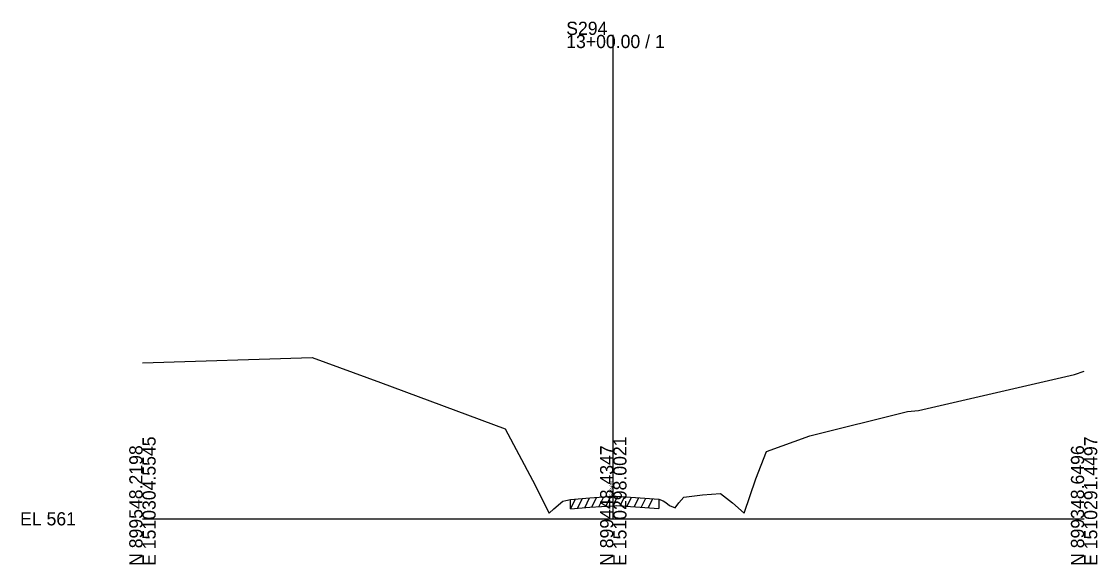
# Model space of a CAD drawing. Extents: x 974 to 2203, y -10 to 19041.
# Drawn here: x 974.3 to 1202.8, y 5990.3 to 6105.6 of the extents above; entities that cross this region are included whole.
import ezdxf

# ---------------------------------------------------------------- set-up
doc = ezdxf.new("R2010")
doc.units = 0
for name, color, linetype in [('RD_GPK_XS_Cell', 7, 'Continuous'), ('RD_XS_ExGround', 7, 'Continuous'), ('RD_XS_ExPaveRet', 7, 'Continuous'), ('RD_XS_TX_Elev_EX', 7, 'Continuous')]:
    doc.layers.add(name, color=color, linetype=linetype)

msp = doc.modelspace()

# ---------------------------------------------------------------- linework, layer by layer
at = {"layer": 'RD_GPK_XS_Cell'}
for p, q in [((1100, 6000), (1100, 6102.73)), ((1000, 6000), (1100, 6000)), ((1100, 6000), (1200, 6000))]:
    msp.add_line(p, q, dxfattribs=at)
at = {"layer": 'RD_XS_ExGround'}
msp.add_lwpolyline([(1000, 6033.09), (1036.04, 6034.24), (1050.58, 6028.97), (1077.02, 6019.13), (1082.85, 6008.21), (1086.36, 6001.19), (1087.39, 6002.09), (1089.31, 6003.76), (1089.89, 6003.9), (1090.93, 6004.11), (1095.05, 6004.45), (1100, 6004.78), (1100.59, 6004.82), (1105.71, 6004.44), (1109.68, 6004.19), (1110.57, 6003.81), (1111.19, 6003.47), (1111.91, 6002.86), (1113.14, 6002.35), (1113.95, 6003.41), (1114.95, 6004.62), (1118.96, 6005.06), (1122.74, 6005.34), (1125.32, 6003.39), (1127.82, 6001.2), (1130.28, 6008.47), (1132.52, 6014.27), (1141.73, 6017.61), (1162.5, 6022.77), (1164.82, 6023.02), (1197.93, 6030.66), (1200, 6031.33)], dxfattribs=at)
at = {"layer": 'RD_XS_ExPaveRet'}
for p, q in [((1090.93, 6002.11), (1091.97, 6004.19)), ((1090.93, 6002.11), (1090.93, 6004.11)), ((1092.43, 6002.23), (1093.47, 6004.32)), ((1093.93, 6002.35), (1094.97, 6004.44)), ((1095.43, 6002.47), (1096.46, 6004.54)), ((1096.93, 6002.57), (1097.96, 6004.64)), ((1098.43, 6002.67), (1099.46, 6004.74)), ((1099.93, 6002.77), (1100.94, 6004.79)), ((1101.43, 6002.76), (1102.39, 6004.69)), ((1102.93, 6002.65), (1103.89, 6004.58)), ((1104.43, 6002.54), (1105.39, 6004.47)), ((1105.93, 6002.43), (1106.89, 6004.37)), ((1107.43, 6002.33), (1108.39, 6004.27)), ((1109.68, 6004.19), (1109.68, 6002.19)), ((1090.93, 6002.11), (1095.05, 6002.45)), ((1095.05, 6002.45), (1100, 6002.78)), ((1100, 6002.78), (1100.59, 6002.82)), ((1100.59, 6002.82), (1105.71, 6002.44)), ((1105.71, 6002.44), (1109.68, 6002.19))]:
    msp.add_line(p, q, dxfattribs=at)

# ---------------------------------------------------------------- texts
at = {"layer": 'RD_GPK_XS_Cell'}
for s, p in [('S294', (1090, 6102.73)), ('13+00.00 / 1', (1090, 6099.93)), ('EL 561', (974, 5998.6))]:
    msp.add_text(s, height=2.8, dxfattribs=at).set_placement(p)
for s, p in [('E 1510304.5545', (1002.8, 5990)), ('E 1510298.0021', (1102.8, 5990)), ('E 1510291.4497', (1202.8, 5990)), ('N 899548.2198', (1000, 5990)), ('N 899448.4347', (1100, 5990)), ('N 899348.6496', (1200, 5990))]:
    msp.add_text(s, height=2.8, rotation=90, dxfattribs=at).set_placement(p)
at = {"layer": 'RD_XS_TX_Elev_EX'}
msp.add_text('563.39', height=0.75, rotation=90, dxfattribs=at).set_placement((1100, 6004.78))

doc.saveas('drawing.dxf')
